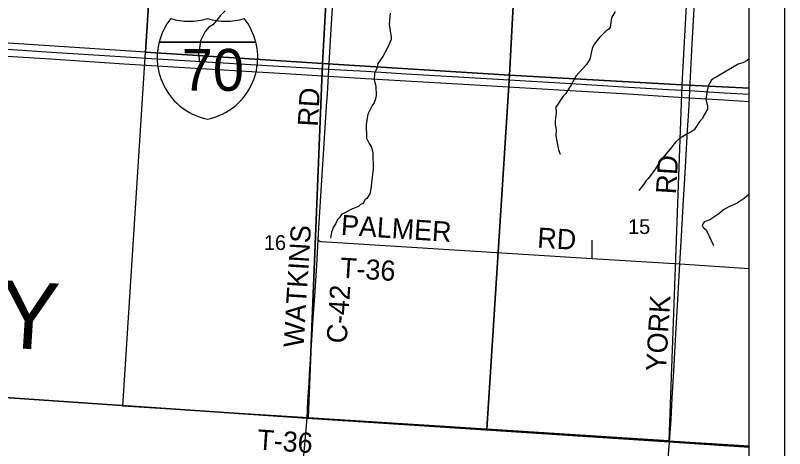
# Model space of a CAD drawing. Extents: x 0 to 34, y 0 to 22.
# Drawn here: x 6.826 to 9, y 15.479 to 16.702 of the extents above; entities that cross this region are included whole.
import ezdxf

# ---------------------------------------------------------------- set-up
doc = ezdxf.new("R2010")
doc.units = 0
for name, color, linetype in [('GM_X_Corporation', 7, 'Continuous'), ('GM_X_County_Road', 7, 'Continuous'), ('GM_X_County_Road_Text', 7, 'Continuous'), ('GM_X_County_Text', 7, 'Continuous'), ('GM_X_Interstate_Location', 7, 'Continuous'), ('GM_X_Interstate_Route', 7, 'Continuous'), ('GM_X_Interstate_Shield', 7, 'Continuous'), ('GM_X_Minor_River', 7, 'Continuous'), ('GM_X_Section', 7, 'Continuous'), ('GM_X_Section_Text', 7, 'Continuous'), ('GM_X_Township_Road', 7, 'Continuous'), ('GM_X_Township_Road_Text', 7, 'Continuous'), ('GM_X_Unincorporated_Text', 7, 'Continuous'), ('SH_Cut_Line', 7, 'Continuous'), ('SH_Data', 7, 'Continuous')]:
    doc.layers.add(name, color=color, linetype=linetype)

msp = doc.modelspace()

# ---------------------------------------------------------------- linework, layer by layer
at = {"layer": 'GM_X_Corporation'}
msp.add_lwpolyline([(6.624, 15.6351), (6.838, 15.6206), (7.6503, 15.5653), (8.6741, 15.4976), (8.9, 15.4827), (8.9, 18.0808), (8.8282, 18.0842), (7.8208, 18.1434), (7.755, 18.1483), (7.0679, 18.1923), (6.7672, 18.2007)], dxfattribs=at)
msp.add_lwpolyline([(4.9875, 14.1), (8.9, 14.1), (8.9, 15.4827), (8.6741, 15.4976), (7.6503, 15.5653), (6.838, 15.6206), (6.624, 15.6351), (6.4, 15.6498), (6.1109, 15.6683), (5.9419, 15.6782), (5.0952, 15.7318), (5.0611, 15.2147)], close=True, dxfattribs=at)
at = {"layer": 'GM_X_County_Road'}
msp.add_line((8.635, 14.9861), (8.6744, 15.4971), dxfattribs=at)
for points in [[(8.6744, 15.4971), (8.6792, 15.5612), (8.6825, 15.6215), (8.6875, 15.714), (8.6897, 15.7521), (8.6958, 15.8509), (8.6996, 15.9173), (8.7039, 16.0007), (8.7092, 16.0954), (8.7136, 16.1658), (8.7187, 16.2571), (8.7239, 16.3435), (8.7265, 16.393), (8.7273, 16.4038), (8.73, 16.4485), (8.7313, 16.4698), (8.7324, 16.4898), (8.7335, 16.5104), (8.7388, 16.6231), (8.7513, 16.8335), (8.7536, 16.8781), (8.7747, 17.2502), (8.7783, 17.3106), (8.7782, 17.3222)], [(7.7068, 16.4655), (7.7106, 16.5304), (7.7116, 16.5509), (7.7183, 16.6638), (7.7222, 16.7232)], [(7.6814, 16.0683), (7.6847, 16.1175), (7.7065, 16.4605), (7.7068, 16.4655)], [(7.6505, 15.5648), (7.6526, 15.613), (7.6565, 15.6633), (7.6577, 15.6895), (7.6614, 15.7435), (7.6647, 15.8005), (7.668, 15.8479), (7.6721, 15.9097), (7.6778, 15.9972), (7.6814, 16.0683)]]:
    msp.add_lwpolyline(points, dxfattribs=at)
at = {"layer": 'GM_X_Interstate_Route'}
for points in [[(6.6872, 16.6147), (6.7745, 16.609), (6.9282, 16.5988), (7.1233, 16.586), (7.1966, 16.5814), (7.3203, 16.5739), (7.5541, 16.5599), (7.6369, 16.555), (7.7116, 16.5509), (7.763, 16.5476), (7.8179, 16.5444), (7.9309, 16.5375), (8.0934, 16.5278), (8.381, 16.5106), (8.5601, 16.5001), (8.6719, 16.4933), (8.7324, 16.4898), (8.7863, 16.4867), (8.8289, 16.4838), (8.9, 16.4798)], [(6.6939, 16.5942), (6.9254, 16.5792), (7.1337, 16.5658), (7.3189, 16.554), (7.5572, 16.54), (7.7106, 16.5304), (7.8168, 16.5243), (7.9297, 16.5174), (8.0923, 16.5078), (8.3775, 16.4913), (8.5578, 16.4804), (8.6708, 16.4732), (8.7313, 16.4698), (8.8282, 16.4636), (8.9, 16.4595)]]:
    msp.add_lwpolyline(points, dxfattribs=at)
at = {"layer": 'GM_X_Interstate_Shield'}
for p, q in [((7.2324, 16.6269), (7.5056, 16.6269)), ((7.5056, 16.6269), (7.2324, 16.6269)), ((7.5056, 16.6269), (7.2324, 16.6269))]:
    msp.add_line(p, q, dxfattribs=at)
for centre, start, end in [((7.4045, 16.5834), 141.669, 165.8066), ((7.3171, 16.8633), 253.0091, 286.9909), ((7.4209, 16.8633), 253.0091, 286.9909), ((7.3335, 16.5834), 14.1934, 38.331), ((7.4045, 16.5834), 165.8066, 258.463), ((7.3335, 16.5834), 281.537, 14.1934)]:
    msp.add_arc(centre, 0.1776, start, end, dxfattribs=at)
at = {"layer": 'GM_X_Minor_River'}
for points in [[(7.4191, 16.7151), (7.4058, 16.7019), (7.3959, 16.6886), (7.3842, 16.6761), (7.3732, 16.6689), (7.3629, 16.6564), (7.3492, 16.6306), (7.3473, 16.6166)], [(7.8856, 16.7084), (7.8825, 16.6769), (7.8885, 16.6408), (7.8877, 16.634), (7.8774, 16.6108), (7.8649, 16.5858), (7.8508, 16.5669), (7.8478, 16.5532), (7.8409, 16.538), (7.8401, 16.5206), (7.8446, 16.5027), (7.8461, 16.4757), (7.8442, 16.4666), (7.84, 16.4553), (7.8355, 16.45), (7.8221, 16.4234), (7.8179, 16.3938), (7.8186, 16.3558), (7.8258, 16.3402), (7.8326, 16.3304), (7.8359, 16.314), (7.8377, 16.2688), (7.8304, 16.2127), (7.8274, 16.1986), (7.8194, 16.1857)], [(8.5214, 16.713), (8.5104, 16.6956), (8.5069, 16.6694), (8.5031, 16.6637), (8.4952, 16.6581), (8.4766, 16.6399), (8.4614, 16.6209), (8.456, 16.6084), (8.4495, 16.5784), (8.4404, 16.564), (8.4112, 16.5314), (8.3968, 16.5064), (8.3816, 16.4821), (8.374, 16.4738), (8.3538, 16.4431), (8.3542, 16.4275), (8.3519, 16.4048), (8.3519, 16.3941), (8.3537, 16.3854), (8.3541, 16.3778), (8.3537, 16.3626), (8.3612, 16.3223), (8.3657, 16.3106)], [(7.3473, 16.6166), (7.3438, 16.5919), (7.3457, 16.582), (7.3453, 16.5706)], [(8.9, 16.5796), (8.8937, 16.5748), (8.8816, 16.5683), (8.8691, 16.565), (8.8065, 16.5279), (8.7986, 16.5245), (8.7929, 16.5188), (8.786, 16.5067), (8.7807, 16.4904), (8.7776, 16.4657), (8.7825, 16.4459), (8.7821, 16.4376), (8.7726, 16.4217), (8.7677, 16.411), (8.7601, 16.4035), (8.7441, 16.3792), (8.7362, 16.3731), (8.7244, 16.3682), (8.702, 16.3542), (8.6918, 16.3444), (8.6842, 16.3345), (8.6808, 16.3288), (8.6497, 16.2925), (8.6348, 16.269), (8.6147, 16.2413), (8.609, 16.236), (8.6022, 16.2254), (8.5878, 16.2079)], [(8.9, 16.1971), (8.8857, 16.1852), (8.866, 16.172), (8.8425, 16.1618), (8.8277, 16.1531), (8.8145, 16.1417), (8.7887, 16.1247), (8.7724, 16.119), (8.7671, 16.1099), (8.7697, 16.1031), (8.778, 16.0966), (8.7988, 16.0522)], [(7.8194, 16.1857), (7.8137, 16.1816), (7.8091, 16.1709), (7.8019, 16.1687), (7.7962, 16.1626), (7.7784, 16.1558), (7.7474, 16.1403), (7.7424, 16.1312), (7.7363, 16.1263), (7.7314, 16.1149), (7.7238, 16.1035), (7.7226, 16.0967), (7.7196, 16.0906), (7.7169, 16.0736)]]:
    msp.add_lwpolyline(points, dxfattribs=at)
at = {"layer": 'GM_X_Section'}
for points in [[(6.7148, 17.6287), (7.2571, 17.593), (7.1941, 16.5986), (6.6627, 16.6332)], [(7.2571, 17.593), (7.7498, 17.5639), (7.694, 16.5662), (7.1941, 16.5986)], [(7.7498, 17.5639), (8.2754, 17.5329), (8.2225, 16.5336), (7.694, 16.5662)], [(8.2754, 17.5329), (8.7642, 17.5047), (8.7092, 16.506), (8.2225, 16.5336)], [(7.1941, 16.5986), (7.694, 16.5662), (7.6539, 15.5659), (7.1295, 15.5991)], [(7.694, 16.5662), (8.2225, 16.5336), (8.1587, 15.5342), (7.6539, 15.5659)], [(8.7092, 16.506), (8.6731, 15.5012), (8.1587, 15.5342), (8.2225, 16.5336)]]:
    msp.add_lwpolyline(points, close=True, dxfattribs=at)
at = {"layer": 'GM_X_Township_Road'}
for p, q in [((8.4561, 16.0154), (8.4561, 16.068)), ((7.606, 15.0546), (7.6505, 15.5648))]:
    msp.add_line(p, q, dxfattribs=at)
for points in [[(7.6505, 15.5648), (7.6526, 15.613), (7.6565, 15.6633), (7.6577, 15.6895), (7.6614, 15.7435), (7.6647, 15.8005), (7.668, 15.8479), (7.6721, 15.9097), (7.6778, 15.9972), (7.6814, 16.0683)], [(7.6814, 16.0683), (7.6844, 16.0655), (7.6886, 16.064), (7.6908, 16.0635), (8.4561, 16.0154), (8.7039, 16.0007), (8.9, 15.9875)], [(6.6243, 15.6345), (6.8382, 15.6201), (7.6505, 15.5648)]]:
    msp.add_lwpolyline(points, dxfattribs=at)
at = {"layer": 'GM_X_Unincorporated_Text'}
for points in [[(8.9, 16.4969), (8.9, 17.4972), (8.7642, 17.5047), (8.7092, 16.506)], [(8.9, 15.4872), (8.9, 16.4969), (8.7092, 16.506), (8.6731, 15.5012)]]:
    msp.add_lwpolyline(points, close=True, dxfattribs=at)
at = {"layer": 'SH_Cut_Line'}
for points in [[(8.9, 15.4827), (8.9, 20.9), (2.1, 20.9), (2.1, 15.9442), (2.2903, 15.9292), (2.5827, 15.9132), (2.6921, 15.9056), (2.7799, 15.8989), (2.8362, 15.8952), (3.3132, 15.8609), (3.9945, 15.8088), (4.2803, 15.787), (4.5905, 15.7634), (4.92, 15.7429), (5.0952, 15.7318), (5.9419, 15.6782), (6.1109, 15.6683), (6.4, 15.6498), (6.624, 15.6351), (6.838, 15.6206), (7.6503, 15.5653), (8.6741, 15.4976)], [(2.1, 15.9442), (2.1, 14.1), (8.9, 14.1), (8.9, 15.4827), (8.6741, 15.4976), (7.6503, 15.5653), (6.838, 15.6206), (6.624, 15.6351), (6.4, 15.6498), (6.1109, 15.6683), (5.9419, 15.6782), (5.0952, 15.7318), (4.92, 15.7429), (4.5905, 15.7634), (4.2803, 15.787), (3.9945, 15.8088), (3.3132, 15.8609), (2.8362, 15.8952), (2.7799, 15.8989), (2.6921, 15.9056), (2.5827, 15.9132), (2.2903, 15.9292)]]:
    msp.add_lwpolyline(points, close=True, dxfattribs=at)
at = {"layer": 'SH_Data'}
msp.add_line((9, 21), (9, 14), dxfattribs=at)

# ---------------------------------------------------------------- texts
at = {"layer": 'GM_X_County_Road_Text'}
for s, rotation, p in [('RD', 86.6032, (7.6805, 16.3872)), ('RD', 86.5452, (8.6929, 16.1963)), ('WATKINS', 86.4606, (7.6404, 15.7631)), ('C-42', 86.2765, (7.7621, 15.7748)), ('YORK', 86.6336, (8.6646, 15.6957))]:
    msp.add_text(s, height=0.05682, rotation=rotation, dxfattribs=at).set_placement(p)
at = {"layer": 'GM_X_County_Text'}
msp.add_text('LICKING COUNTY', height=0.189394, rotation=356.3996, dxfattribs=at).set_placement((4.7947, 15.8905))
at = {"layer": 'GM_X_Interstate_Location'}
for s in ['.', '-', ',']:
    msp.add_text(s, height=0.000189, dxfattribs=at).set_placement((7.369, 16.5514))
msp.add_text('70', height=0.000189, rotation=0, dxfattribs=at).set_placement((7.3303, 16.5121))
at = {"layer": 'GM_X_Interstate_Shield'}
msp.add_text('70', height=0.11837, dxfattribs=at).set_placement((7.2962, 16.4893))
at = {"layer": 'GM_X_Section_Text'}
for s, p in [('15', (8.5578, 16.085)), ('16', (7.5286, 16.0398))]:
    msp.add_text(s, height=0.04186, rotation=0, dxfattribs=at).set_placement(p)
at = {"layer": 'GM_X_Township_Road_Text'}
for s, rotation, p in [('PALMER', 356.2761, (7.745, 16.0826)), ('RD', 356.5467, (8.2999, 16.0468)), ('T-36', 356.4684, (7.7425, 15.9618)), ('T-36', 356.115, (7.5085, 15.4767))]:
    msp.add_text(s, height=0.05682, rotation=rotation, dxfattribs=at).set_placement(p)

doc.saveas('drawing.dxf')
